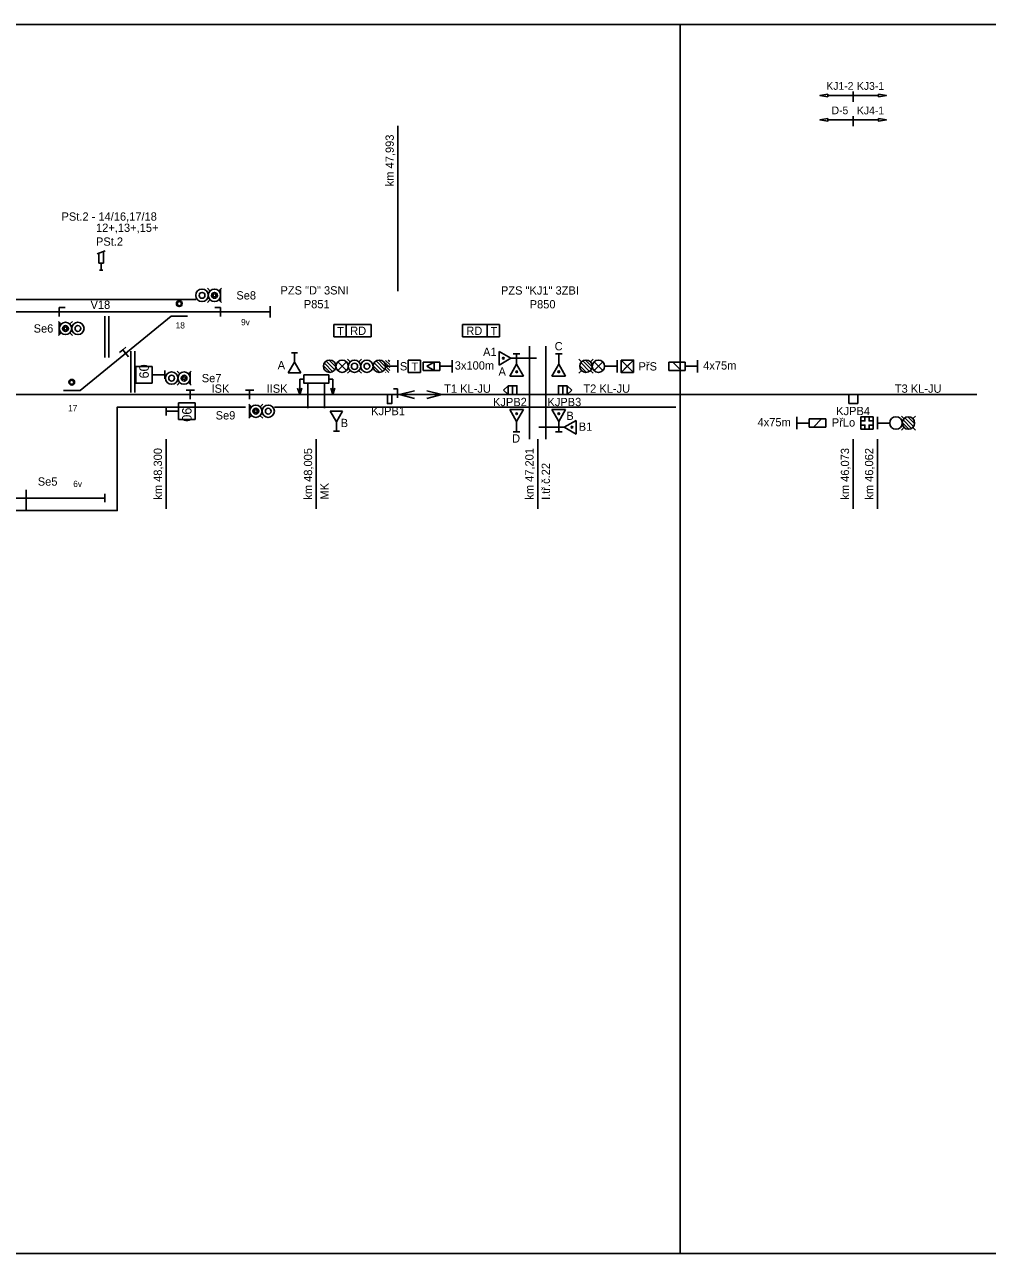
# Model space of a CAD drawing. Extents: x -1146 to 534, y 4 to 301.
# Drawn here: x -44.4 to 188.3, y 4.4 to 301.4 of the extents above; entities that cross this region are included whole.
import ezdxf

# ---------------------------------------------------------------- set-up
doc = ezdxf.new("R2010")
doc.units = 0
for name, color, linetype in [('1', 7, 'Continuous'), ('formát tisku', 7, 'Continuous'), ('kabel', 7, 'Continuous'), ('koleje', 7, 'Continuous'), ('návěstidla', 7, 'Continuous'), ('ostatní', 7, 'Continuous'), ('popisy', 7, 'Continuous'), ('čd', 7, 'Continuous')]:
    doc.layers.add(name, color=color, linetype=linetype)

# ---------------------------------------------------------------- blocks, each defined once
blk = doc.blocks.new('NS1')
for p, q in [((-1, 2.5), (-1.7, 3.2)), ((1, 2.5), (1.7, 3.2)), ((-1, 0.5), (-1.7, -0.2)), ((-1.5, 0), (1.5, 0)), ((1, 0.5), (1.7, -0.2))]:
    blk.add_line(p, q)
for centre, radius in [((0, 4.5), 1.5), ((0, 1.5), 1.5), ((0, 4.5), 0.7)]:
    blk.add_circle(centre, radius)
for start, end in [(0, 180), (180, 0)]:
    blk.add_arc((0, 1.5), 0.375, start, end)
blk = doc.blocks.new('SB4')
for q in [(-1.39, 1.08), (0, -1.08)]:
    blk.add_line((0, 1.08), q)
blk = doc.blocks.new('NS16')
for p, q in [((-1.499, 0.6437), (-1.1298, 1.0129)), ((-1.4356, 0), (-0.4227, 1.0129)), ((-0.7285, 0), (0.2844, 1.0129)), ((-0.0214, 0), (0.9915, 1.0129)), ((0.6857, 0), (1.499, 0.8133)), ((1.3928, 0), (1.499, 0.1062))]:
    blk.add_line(p, q)
blk = doc.blocks.new('SB1')
for p, q in [((0, 1.08), (-1, 1.08)), ((1, 1.08), (0, 1.08)), ((0, 1.08), (0, -1.08))]:
    blk.add_line(p, q)
blk = doc.blocks.new('PZ2')
for start, end in [(0, 180), (180, 0)]:
    blk.add_arc((0, 2), 0.5, start, end)
blk = doc.blocks.new('O8')
for p, q in [((1.25, 6.25), (-1.25, 5.25)), ((-0.75, 5.45), (-0.75, 2.25)), ((0.75, 2.25), (0.75, 6.05)), ((-0.75, 2.25), (0.75, 2.25)), ((-0.5, 0), (0.5, 0)), ((0, 2.25), (0, 0))]:
    blk.add_line(p, q)
blk = doc.blocks.new('P2')
for p, q in [((2, 6.5), (-2, 6.5)), ((-0.02, 3.02), (-2, 6.5)), ((2, 6.5), (0.02, 3.02)), ((1, 0), (-1, 0)), ((0, 3), (0, 0))]:
    blk.add_line(p, q)
blk = doc.blocks.new('Z22')
for p, q in [((0, 5), (-0.69, 2.9)), ((0, 0), (0, 5)), ((0, 5), (0.69, 2.9))]:
    blk.add_line(p, q)
blk = doc.blocks.new('U3')
at = {"layer": '1'}
for p, q in [((1.0002, 4), (-1.0002, 4)), ((-1.0002, 4), (-1.0002, 0)), ((-1.0002, 1.0002), (1.0002, 3.0002)), ((1.0002, 0), (1.0002, 4)), ((-1.0002, 0), (1.0002, 0))]:
    blk.add_line(p, q, dxfattribs=at)
blk = doc.blocks.new('P3')
for p, q in [((-2, 6.5), (-0.02, 3.02)), ((-2, 6.5), (2, 6.5)), ((0.02, 3.02), (2, 6.5)), ((1.6, 1.3), (-5.8, 1.3)), ((-1, 0), (1, 0)), ((0, 3), (0, 0)), ((5.1, 3.3), (1.62, 1.32)), ((1.62, 1.28), (5.1, -0.7)), ((5.1, 3.3), (5.1, -0.7))]:
    blk.add_line(p, q)
for centre, start, end in [((-0.02, 5.27), 90, 270), ((-0.02, 5.27), 270, 90), ((3.87, 1.32), 0, 180), ((3.87, 1.32), 180, 0)]:
    blk.add_arc(centre, 0.25, start, end)
blk = doc.blocks.new('P1')
for p, q in [((-0.02, 3.02), (-2, 6.5)), ((2, 6.5), (-2, 6.5)), ((2, 6.5), (0.02, 3.02)), ((1, 0), (-1, 0)), ((0, 3), (0, 0))]:
    blk.add_line(p, q)
for start, end in [(90, 270), (270, 90)]:
    blk.add_arc((0.02, 5.27), 0.25, start, end)
blk = doc.blocks.new('SPN1right')
for p, q in [((-1.08, 2.16), (1.08, 2.16)), ((-1.08, 0), (-1.08, 2.16)), ((-1.08, 2.16), (0, 2.16)), ((-1.08, 0), (-1.08, 2.16)), ((1.08, 0), (-1.08, 0)), ((0, 0), (-1.08, 0)), ((0, 2.16), (0, 0)), ((1.08, 2.16), (1.08, 0)), ((2.16, 1.08), (1.08, 2.16)), ((1.08, 0), (2.16, 1.08))]:
    blk.add_line(p, q)
blk.add_lwpolyline([(0, 2.16), (-1.08, 2.16), (-1.08, 0), (0, 0)], close=True)
blk = doc.blocks.new('SB11b')
for p, q in [((-1.5, 0), (1.5, 0)), ((1.5, 0), (1.5, -3))]:
    blk.add_line(p, q)
blk.add_lwpolyline([(1.5, 0), (0, 0), (0, -0.375), (0, -3), (1.5, -3)], close=True)
blk = doc.blocks.new('O9')
for p, q in [((-1.5, 3), (-1.5, 0)), ((1.5, 3), (-1.5, 3)), ((1.5, 0), (1.5, 3)), ((-1.5, 0), (1.5, 0))]:
    blk.add_line(p, q)
blk.add_text('T', height=2).set_placement((-0.68, 0.41))
blk = doc.blocks.new('O10')
for p, q in [((3, 3), (-3, 3)), ((-3, 3), (-3, 0)), ((3, 0), (3, 3)), ((-3, 0), (3, 0))]:
    blk.add_line(p, q)
blk.add_text('RD', height=2).set_placement((-2.05, 0.5))
blk = doc.blocks.new('U7')
for p, q in [((-1, 4), (-1, 0)), ((1, 4), (-1, 4)), ((-1, 1.41), (0, 3.15)), ((0, 3.15), (1, 1.41)), ((1, 0), (1, 4)), ((-1, 1.41), (1, 1.41)), ((-1, 0), (1, 0))]:
    blk.add_line(p, q)
blk = doc.blocks.new('U10')
at = {"layer": '1'}
for p, q in [((-6.9999, -2), (-6.9999, 2)), ((-6.9999, 2), (-3, 2)), ((-3, 2), (-3, -2)), ((0, 0), (-3, 0)), ((0, -1), (0, 1)), ((-3, -2), (-6.9999, -2))]:
    blk.add_line(p, q, dxfattribs=at)

msp = doc.modelspace()

# ---------------------------------------------------------------- linework, layer by layer
for p, q in [((114.04, 301.44), (114.04, 292.56)), ((30.59, 218), (28.5, 220.09)), ((30.85, 218.74), (29.24, 220.35)), ((34.35, 219.86), (33.65, 220.56)), ((36.35, 219.86), (37.05, 220.56)), ((40.6, 220.16), (42.63, 218.08)), ((41.26, 220.35), (42.85, 218.76)), ((45.85, 217.36), (45.85, 220.36)), ((58.99, 217.36), (58.99, 220.36)), ((90.31, 219.86), (89.61, 220.56)), ((90.56, 220.16), (92.61, 218.06)), ((91.21, 220.36), (92.81, 218.76)), ((92.31, 219.86), (93.01, 220.56)), ((98.81, 217.36), (98.81, 220.36)), ((99.8, 220.36), (102.8, 220.36)), ((99.8, 217.36), (99.8, 220.36)), ((99.8, 220.36), (102.8, 217.36)), ((102.8, 220.36), (99.8, 217.36)), ((102.8, 220.36), (102.8, 217.36)), ((118.3, 217.36), (118.3, 220.36)), ((29.43, 217.36), (27.85, 218.93)), ((30.09, 217.55), (28.06, 219.62)), ((34.35, 217.86), (33.65, 217.16)), ((36.35, 217.86), (37.05, 217.16)), ((39.85, 218.96), (41.45, 217.36)), ((40.11, 219.7), (42.19, 217.61)), ((42.85, 218.86), (45.85, 218.86)), ((55.99, 218.86), (58.99, 218.86)), ((90.31, 217.86), (89.61, 217.16)), ((89.81, 218.96), (91.41, 217.36)), ((90.11, 219.66), (92.11, 217.66)), ((92.31, 217.86), (93.01, 217.16)), ((95.81, 218.86), (98.81, 218.86)), ((102.8, 217.36), (99.8, 217.36)), ((115.3, 218.86), (118.3, 218.86)), ((45.76, 213.37), (44.76, 213.37)), ((45.76, 213.37), (45.76, 211.22)), ((46.21, 212), (49.84, 212.95)), ((46.21, 212), (49.84, 211.05)), ((56.5, 212), (52.87, 212.95)), ((56.5, 212), (52.87, 211.05)), ((154.82, 212), (156.98, 212)), ((155.9, 212), (154.82, 212)), ((154.82, 212), (154.82, 209.84)), ((156.98, 212), (155.9, 212)), ((156.98, 209.84), (156.98, 212)), ((156.98, 212), (156.98, 209.84)), ((154.82, 209.84), (156.98, 209.84)), ((142.27, 203.64), (142.27, 206.64)), ((145.27, 205.14), (142.27, 205.14)), ((157.74, 206.64), (160.74, 206.64)), ((157.74, 203.64), (157.74, 206.64)), ((157.74, 205.64), (158.74, 205.64)), ((158.74, 205.64), (158.74, 206.64)), ((159.74, 206.64), (159.74, 205.64)), ((159.74, 205.64), (160.74, 205.64)), ((160.74, 206.64), (160.74, 203.64)), ((161.74, 206.64), (161.74, 203.64)), ((164.74, 205.14), (161.74, 205.14)), ((168.24, 206.14), (167.54, 206.84)), ((169.34, 203.64), (167.74, 205.24)), ((169.99, 203.84), (167.94, 205.94)), ((170.44, 204.34), (168.44, 206.34)), ((170.74, 205.04), (169.14, 206.64)), ((170.24, 206.14), (170.94, 206.84)), ((158.74, 204.64), (157.74, 204.64)), ((160.74, 203.64), (157.74, 203.64)), ((158.74, 203.64), (158.74, 204.64)), ((160.74, 204.64), (159.74, 204.64)), ((159.74, 204.64), (159.74, 203.64)), ((168.24, 204.14), (167.54, 203.44)), ((170.24, 204.14), (170.94, 203.44)), ((114.04, 4.44), (114.04, 13.33))]:
    msp.add_line(p, q)
for centre, radius in [((-7, 234), 0.7), ((1.5, 236), 0.7), ((-34.5, 228), 0.7), ((29.35, 218.86), 1.5), ((32.35, 218.86), 1.5), ((35.35, 218.86), 1.5), ((38.35, 218.86), 1.5), ((41.35, 218.86), 1.5), ((71.32, 220.8), 0.207), ((91.31, 218.86), 1.5), ((94.31, 218.86), 1.5), ((38.35, 218.86), 0.7), ((74.54, 217.53), 0.207), ((84.72, 217.53), 0.207), ((-33, 215), 0.7), ((-5.85, 216), 0.7), ((11.5, 208), 0.7), ((74.54, 207.41), 0.207), ((84.72, 207.41), 0.207), ((166.24, 205.14), 1.5), ((169.24, 205.14), 1.5), ((87.93, 204.14), 0.207)]:
    msp.add_circle(centre, radius)
for start, end in [(90, 270), (270, 90)]:
    msp.add_arc((35.35, 218.86), 0.75, start, end)
at = {"layer": 'formát tisku'}
for points in [[(-95.96, 301.44), (114.04, 301.44), (114.04, 4.44), (-95.96, 4.44)], [(114.04, 301.44), (324.04, 301.44), (324.04, 4.44), (114.04, 4.44)]]:
    msp.add_lwpolyline(points, close=True, dxfattribs=at)
at = {"layer": 'kabel'}
for p, q in [((-79, 235), (-3, 235)), ((16, 209), (113, 209)), ((-44, 189), (-44, 184))]:
    msp.add_line(p, q, dxfattribs=at)
msp.add_lwpolyline([(-82, 184), (-22, 184), (-22, 209), (9, 209)], dxfattribs=at)
at = {"layer": 'koleje'}
for p, q in [((15, 232), (-90, 232)), ((-31, 213), (-9, 231)), ((-25, 231), (-25, 221)), ((-24, 231), (-24, 221)), ((-9, 231), (-5, 231)), ((-18.73, 222.54), (-18.73, 212.54)), ((-17.73, 222.54), (-17.73, 212.54)), ((-128.93, 212), (185.81, 212)), ((-35, 213), (-31, 213)), ((-25, 188), (-25, 186)), ((-95, 187), (-25, 187))]:
    msp.add_line(p, q, dxfattribs=at)
at = {"layer": 'návěstidla'}
for p, q in [((31.29, 219.92), (33.41, 217.8)), ((31.29, 217.8), (33.41, 219.92)), ((93.25, 219.92), (95.37, 217.8)), ((93.25, 217.8), (95.37, 219.92))]:
    msp.add_line(p, q, dxfattribs=at)
at = {"layer": 'ostatní'}
for p, q in [((77.63, 201.24), (77.63, 223.7)), ((81.63, 223.7), (81.63, 201.24)), ((24.11, 208.76), (24.11, 214.76)), ((28.11, 214.76), (28.11, 208.76))]:
    msp.add_line(p, q, dxfattribs=at)
at = {"layer": 'popisy'}
for p, q in [((155.9, 282.8), (155.9, 285.27)), ((155.9, 282.8), (155.9, 285.27)), ((149.73, 284.33), (155.98, 284.33)), ((162.05, 284.33), (155.8, 284.33)), ((155.9, 276.87), (155.9, 279.34)), ((155.9, 276.87), (155.9, 279.34)), ((45.85, 237), (45.85, 277)), ((149.73, 278.4), (155.98, 278.4)), ((162.05, 278.4), (155.8, 278.4)), ((-10.19, 184.38), (-10.19, 201.24)), ((26.11, 184.38), (26.11, 201.24)), ((79.63, 184.38), (79.63, 201.24)), ((155.9, 184.38), (155.9, 201.24)), ((161.74, 184.38), (161.74, 201.24))]:
    msp.add_line(p, q, dxfattribs=at)
for points in [[(149.73, 284.64), (149.73, 284.02), (147.85, 284.33)], [(162.05, 284.64), (162.05, 284.02), (163.93, 284.33)], [(149.73, 278.72), (149.73, 278.09), (147.85, 278.4)], [(162.05, 278.72), (162.05, 278.09), (163.93, 278.4)]]:
    msp.add_lwpolyline(points, close=True, dxfattribs=at)
at = {"layer": 'čd'}
for p, q in [((15, 230.61), (15, 233.39)), ((22.11, 215.76), (23.11, 215.76)), ((29.11, 215.76), (30.11, 215.76))]:
    msp.add_line(p, q, dxfattribs=at)
for points in [[(99.8, 220.36), (99.8, 217.36), (101.3, 218.86)], [(102.8, 217.36), (102.8, 220.36), (101.3, 218.86)], [(23.11, 216.76), (29.11, 216.76), (29.11, 214.76), (23.11, 214.76)], [(160.74, 205.64), (159.74, 205.64), (159.74, 206.64), (158.74, 206.64), (158.74, 205.64), (157.74, 205.64), (157.74, 204.64), (158.74, 204.64), (158.74, 203.64), (159.74, 203.64), (159.74, 204.64), (160.74, 204.64)]]:
    msp.add_lwpolyline(points, close=True, dxfattribs=at)

# ---------------------------------------------------------------- block references
for name, p, xscale, yscale in [('O8', (-25.88, 242.06), 0.7499999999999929, 0.7499999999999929), ('SB11b', (43.29, 212), 0.72, 0.72)]:
    msp.add_blockref(name, p, dxfattribs=dict(xscale=xscale, yscale=yscale))
at = {"yscale": -1, "rotation": 180}
msp.add_blockref('SPN1right', (73.54, 212), dxfattribs=at)
msp.add_blockref('SPN1right', (85.71, 212))
at = {"layer": 'návěstidla'}
for name, p, rotation in [('NS1', (3, 236), 90.00000000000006), ('NS1', (-36, 228), -89.99999999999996), ('NS16', (42.85, 218.86), -90.00000000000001), ('NS1', (-4.35, 216), 90.00000000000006), ('NS1', (10, 208), -89.99999999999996)]:
    msp.add_blockref(name, p, dxfattribs=dict(at, rotation=rotation))
at = {"layer": 'návěstidla', "xscale": 0.7499999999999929, "yscale": 0.7499999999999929, "rotation": 180}
msp.add_blockref('P2', (20.85, 222.14), dxfattribs=at)
at = {"layer": 'návěstidla', "xscale": 0.7499999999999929, "yscale": 0.7499999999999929}
msp.add_blockref('P2', (30.99, 203.16), dxfattribs=at)
at = {"layer": 'čd', "yscale": -1}
for name, p, rotation in [('SB4', (-36, 232), 180), ('U3', (145.27, 205.14), 89.99999999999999)]:
    msp.add_blockref(name, p, dxfattribs=dict(at, rotation=rotation))
at = {"layer": 'čd'}
for name, p in [('PZ2', (-7, 232)), ('SB4', (3, 232)), ('O9', (31.86, 225.94)), ('O10', (36.36, 225.94)), ('O10', (64.43, 225.94)), ('O9', (68.93, 225.94)), ('O9', (49.8, 217.36)), ('U10', (-10.52, 216.81)), ('PZ2', (-33, 213)), ('SB1', (-4.35, 212)), ('SB1', (10, 212))]:
    msp.add_blockref(name, p, dxfattribs=at)
for name, p, rotation in [('SB1', (-20, 222), 39.28940686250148), ('U7', (55.99, 218.86), 90), ('U3', (115.3, 218.86), 89.99999999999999), ('U10', (-10.19, 208), 179.9999999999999)]:
    msp.add_blockref(name, p, dxfattribs=dict(at, rotation=rotation))
at = {"layer": 'čd', "rotation": 180}
for name, p, xscale, yscale in [('P3', (74.52, 221.89), 0.827875, 0.827875), ('P1', (84.73, 221.89), 0.827875, 0.827875), ('Z22', (22.11, 215.76), 0.7499999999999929, 0.7499999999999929), ('Z22', (30.11, 215.76), 0.7499999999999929, 0.7499999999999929)]:
    msp.add_blockref(name, p, dxfattribs=dict(at, xscale=xscale, yscale=yscale))
at = {"layer": 'čd', "xscale": 0.827875, "yscale": 0.827875}
for name, p in [('P1', (74.52, 203.05)), ('P3', (84.73, 203.05))]:
    msp.add_blockref(name, p, dxfattribs=at)

# ---------------------------------------------------------------- texts
for s, height, p in [('KJ1-2', 1.875, (149.41, 285.68)), ('KJ3-1', 1.875, (156.81, 285.67)), ('D-5', 1.875, (150.67, 279.77)), ('KJ4-1', 1.875, (156.81, 279.74)), ('PSt.2 - 14/16,17/18', 2, (-35.47, 254.05)), ('12+,13+,15+', 2, (-27.13, 251.34)), ('PSt.2', 2, (-27.14, 248)), ('18', 1.5, (-7.88, 228)), ('9v', 1.5, (7.93, 228.77)), ('KJPB2', 2, (68.83, 209.23)), ('KJPB3', 2, (81.99, 209.23)), ('17', 1.5, (-33.88, 208)), ('KJPB1', 2, (39.38, 207.04)), ('KJPB4', 2, (151.79, 207.05)), ('6v', 1.5, (-32.63, 189.69))]:
    msp.add_text(s, height=height).set_placement(p)
at = {"layer": '1'}
for s, rotation, p in [('60', 90, (-14.37, 215.91)), ('90', 270, (-6.34, 208.88))]:
    msp.add_text(s, height=2.3, rotation=rotation, dxfattribs=at).set_placement(p)
at = {"layer": 'popisy'}
for s, p in [('km 47,993', (44.85, 262.37)), ('km 48,300', (-11.19, 186.61)), ('km 48,005', (25.11, 186.61)), ('km 47,201', (78.63, 186.61)), ('km 46,073', (154.9, 186.61)), ('km 46,062', (160.74, 186.61)), ('I.tř.č.22', (82.59, 186.57)), ('MK', (29.08, 186.64))]:
    msp.add_text(s, height=2, rotation=90, dxfattribs=at).set_placement(p)
for s, p in [('PZS "D" 3SNI', (17.46, 236.21)), ('PZS "KJ1" 3ZBI', (70.75, 236.19)), ('V18', (-28.46, 232.73)), ('Se8', (6.79, 235)), ('P851', (23.1, 232.88)), ('P850', (77.7, 232.85)), ('Se6', (-42.21, 227)), ('A1', (66.43, 221.33)), ('C', (83.74, 222.71)), ('A', (16.78, 218.14)), ('S', (46.32, 217.86)), ('3x100m', (59.59, 218.06)), ('PřS', (104.01, 217.84)), ('4x75m', (119.64, 218.06)), ('Se7', (-1.57, 215)), ('A', (70.16, 216.59)), ('ISK', (0.79, 212.46)), ('IISK', (14.11, 212.46)), ('T1 KL-JU', (57.03, 212.46)), ('T2 KL-JU', (90.67, 212.46)), ('T3 KL-JU', (165.96, 212.46)), ('Se9', (1.79, 206)), ('B', (86.56, 205.9)), ('B', (32.01, 204.16)), ('B1', (89.56, 203.27)), ('4x75m', (132.78, 204.35)), ('PřLo', (150.72, 204.29)), ('D', (73.45, 200.41)), ('Se5', (-41.21, 190))]:
    msp.add_text(s, height=2, dxfattribs=at).set_placement(p)

doc.saveas('drawing.dxf')
